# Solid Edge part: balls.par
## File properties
Title: Bearing
Author: Deepak Maini
Template: Normal.par
Last saved by: Robert a Rhodes jr
Revision: 7
Application: Solid Edge
Material: aluminum
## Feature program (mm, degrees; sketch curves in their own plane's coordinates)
sketch for "unnamed RevolvedProtrusion 1" plane through (0, 0, 0) normal (0, -1, 0) x-axis (1, 0, 0)
  arc centre (0, 0) radius 6.604 from (0, 6.604) to (0, -6.604) cw
  line (0, 6.604) -> (0, -6.604)
  dimension (radial) = 0
revolve "unnamed RevolvedProtrusion 1" add full turn 360 deg
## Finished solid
Body 1: solid body, 1 face, 0 edges, 0 vertices.
  Faces by surface: sphere 1
Spherical faces by radius (mm): R6.604 x1
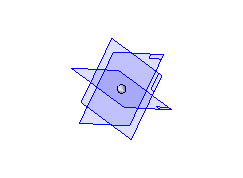
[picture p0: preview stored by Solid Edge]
